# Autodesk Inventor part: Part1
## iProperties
Author: Jan
Created: 2002-05
Part Number: Part1
Document SubType Name: Modeling
Designer: Jan
Control State: 0
Master: False
Checked Out: False
PropertySet Name: Design Tracking Control
Shininess: 64.0
Angle Display Precision: 2
Document Length Units: 11269
Document Angle Units: 11283
Document Time Units: 11279
Document Mass Units: 11290
Document Length Units Precision: 3
Document Angle Units Precision: 2
Compacted: False
PropertySet Name: _Private Model Information
Density: 0.0
Volumn: 0.0
Area: 0.0
PropertySet Name: Model Information
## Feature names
1. Extrusion1
2. Shell1
